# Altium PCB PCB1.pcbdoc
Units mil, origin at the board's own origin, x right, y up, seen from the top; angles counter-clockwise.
Board outline 5280 x 4787.5 mil, 2 copper layers (Top Layer, Bottom Layer); 106 components, 47 nets, 277 pads, 72 vias.
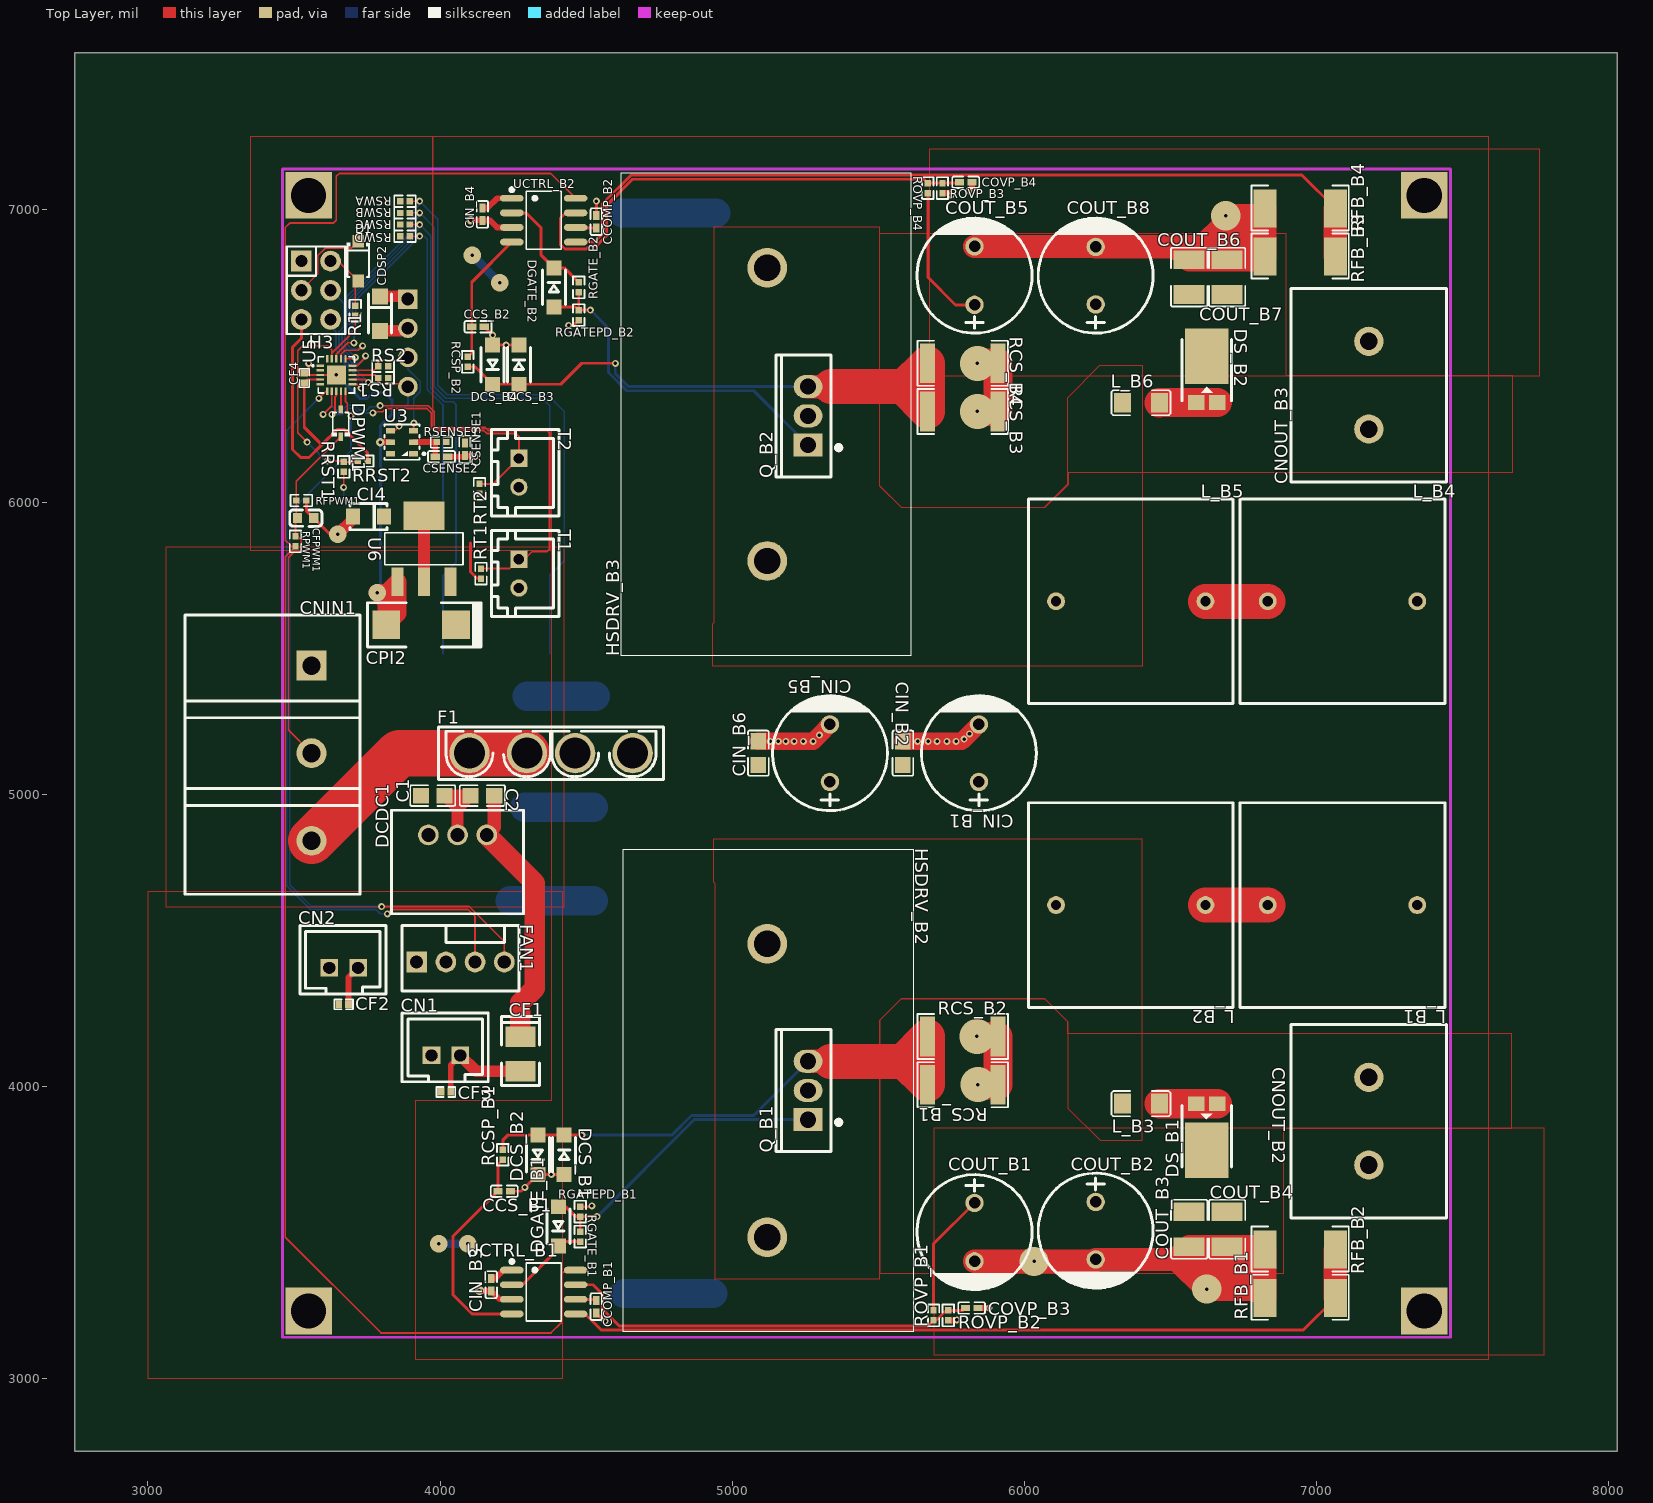
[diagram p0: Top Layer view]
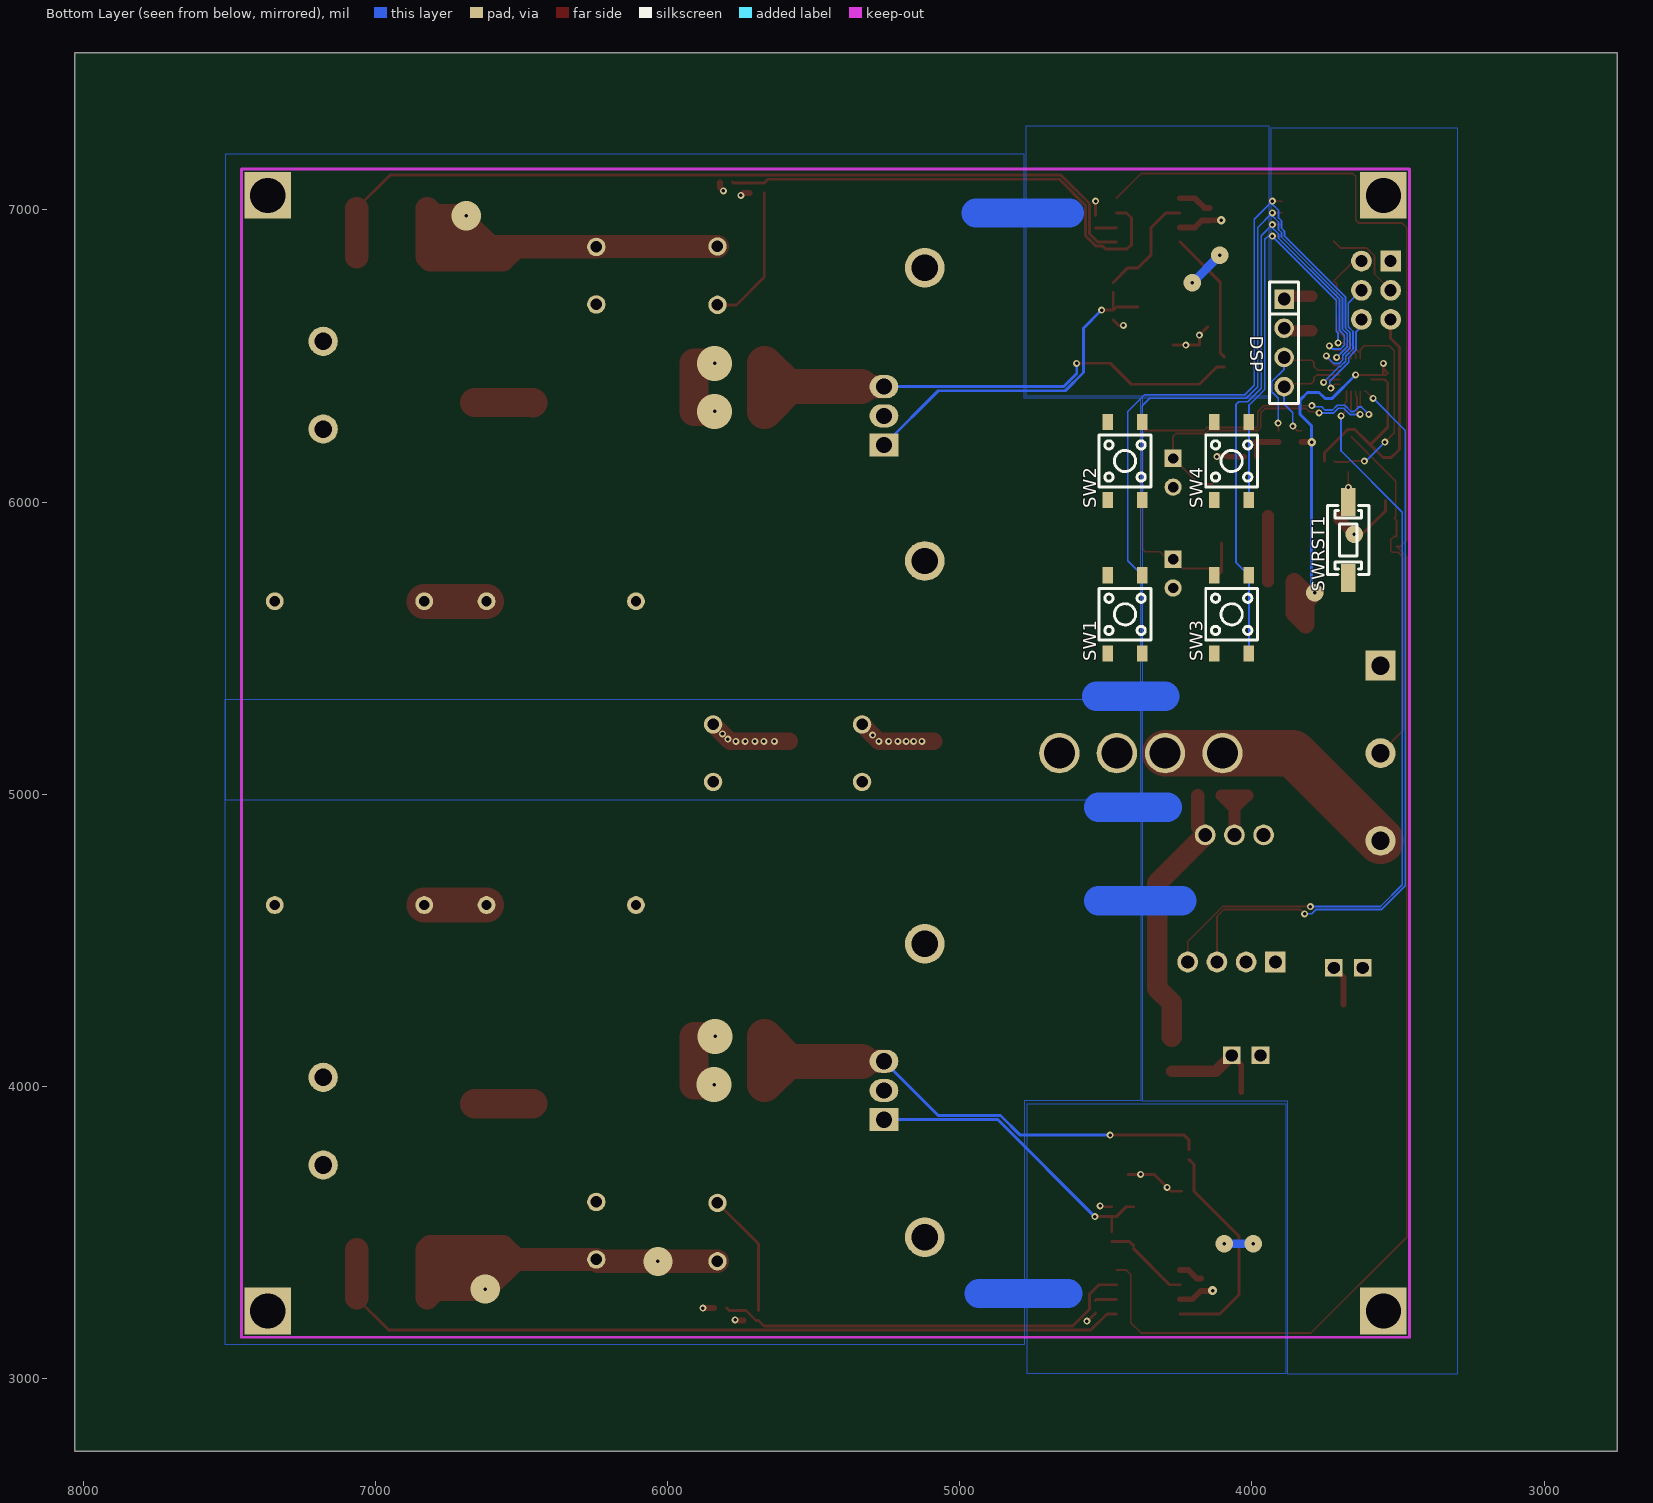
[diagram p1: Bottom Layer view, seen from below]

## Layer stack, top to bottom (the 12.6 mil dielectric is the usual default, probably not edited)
Top Layer: signal copper (thickness not stored)
Dielectric: dielectric 12.6, FR-4, Dk 4.8
Bottom Layer: signal copper (thickness not stored)

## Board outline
8030,2750 2750,2750 2750,7537.5 8030,7537.5

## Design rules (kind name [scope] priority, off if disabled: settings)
Clearance copperThickness1oz [All] p1: gap=7 ignorepadtopadclearanceinfootprint=FALSE except(1: Track-Sheet SMDPad-Sheet THPad-Sheet Via-Sheet Fill-Sheet Region-Sheet Poly-Sheet Text-Sheet Sheet-Hole; 4: Track-Track; 6: Track-SMDPad SMDPad-SMDPad Track-THPad SMDPad-THPad THPad-THPad Track-Via SMDPad-Via THPad-Via Via-Via Track-Fill SMDPad-Fill THPad-Fill Via-Fill Fill-Fill SMDPad-Region THPad-Region Via-Region Fill-Region Region-Region Track-Poly SMDPad-Poly THPad-Poly Via-Poly Fill-Poly Poly-Poly Track-Text SMDPad-Text THPad-Text Via-Text Fill-Text Region-Text Poly-Text Text-Text Track-Hole SMDPad-Hole THPad-Hole Via-Hole Fill-Hole Region-Hole Poly-Hole Text-Hole; 11.8: Track-Region Region-Poly)
Clearance copperThickness2oz [All] p1: gap=7 ignorepadtopadclearanceinfootprint=FALSE except(6: Track-SMDPad SMDPad-SMDPad Track-THPad SMDPad-THPad THPad-THPad Track-Via SMDPad-Via THPad-Via Via-Via Track-Fill SMDPad-Fill THPad-Fill Via-Fill Fill-Fill SMDPad-Region THPad-Region Via-Region Fill-Region Region-Region Track-Poly SMDPad-Poly THPad-Poly Via-Poly Fill-Poly Poly-Poly Track-Text SMDPad-Text THPad-Text Via-Text Fill-Text Region-Text Poly-Text Text-Text Track-Hole SMDPad-Hole THPad-Hole Via-Hole Fill-Hole Region-Hole Poly-Hole Text-Hole; 8: Track-Track; 11.8: Track-Region Region-Poly Track-Sheet SMDPad-Sheet THPad-Sheet Via-Sheet Fill-Sheet Region-Sheet Poly-Sheet Text-Sheet Sheet-Hole)
DiffPairsRouting differentialPair [All] p1: maxuncoupledlength=10 maxlimit=6 mostfreqgap=6 toplayer_minwidth=5 toplayer_prefwidth=10 toplayer_maxwidth=100 bottomlayer_minwidth=5 bottomlayer_prefwidth=10 bottomlayer_maxwidth=100
PasteMaskExpansion pasteMaskExpansion [All] p1:
PlaneConnect innerPlane [All] p1: planeconnectstyle=Relief reliefexpansion=20 reliefentries=4 reliefconductorwidth=10 reliefairgap=10
PolygonConnect copperRegion [All] p1: connectstyle=Relief reliefentries=4 reliefconductorwidth=10 polygonreliefangle="90 Angle" airgapwidth=10
RoutingVias viaSize [All] p1: viastyle="Through Hole" holewidth=12 minholewidth=11.8 maxholewidth=248 width=24 minwidth=19.7 maxwidth=393.7
SolderMaskExpansion solderMaskExpansion [All] p1: useseparateexpansions=TRUE expansion=2 expansionbottom=2
Width copperThickness1oz [All] p1: maxlimit=200 minlimit=5 preferedwidth=10
Width copperThickness2oz [All] p1: maxlimit=100 minlimit=8 preferedwidth=10

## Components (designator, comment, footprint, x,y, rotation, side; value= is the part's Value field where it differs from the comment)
C1 "CGA0805X5R226M350MT" C0805 3975,4995 r0 top
C2 "CL21A226MAYNNNE" C0805 4145,4995 r180 top
CCOMP_B1 "CL05A224KA5NNNC" C0402 4535,3245 r270 top
CCOMP_B2 "CL05A224KA5NNNC" C0402 4535,6960 r90 top
CCS_B1 "TCC0402COG101K500AT" C0402 4220,3640 r0 top
CCS_B2 "TCC0402COG101K500AT" C0402 4130,6600 r0 top
CDSP2 "10uF" CAP-SMD_L3.2-W1.6-R-RD 3795,6645 r90 top
CF1 "10uF" CAP-SMD_L3.5-W2.8 4275,4110 r270 top
CF2 "1uF" 0402 3670,4280 r0 top
CF3 "1uF" 0402 4020,3980 r0 top
CF4 "1uF" 0402 3535,6425 r90 top
CFPWM1 "FN18X102K500PSG" C0603 3540,5945 r180 top
CI4 "10uF" CAP-SMD_L3.2-W1.6 3755,5950 r180 top
CIN_B1 "1010631012R00" CAP-TH_BD10.0-P5.00-D0.6-FD-A 5845,5140 r90 top
CIN_B2 "CL21A106KAYNNNE_C15850" C0805 5585,5140 r90 top
CIN_B3 "CL05A105KA5NQNC" C0402 4175,3320 r90 top
CIN_B4 "CL05A105KA5NQNC" C0402 4145,6985 r90 top
CIN_B5 "1010631012R00" CAP-TH_BD10.0-P5.00-D0.6-FD-A 5335,5140 r90 top
CIN_B6 "CL21A106KAYNNNE_C15850" C0805 5090,5140 r90 top
CN1 "WAFER-XH2.54-2PZZ" CONN-TH_XH2.54-2P 4020,4105 r0 top
CN2 "WAFER-XH2.54-2PZZ" CONN-TH_XH2.54-2P 3670,4405 r0 top
CNIN1 "DBT50G-7.62-3P-BK-P" CONN-TH_3P-P7.62_L15.2-W24.4-EX4.2 3560,5140 r270 top
CNOUT_B2 "WJ25C-B-2P" CONN-TH_2P-P7.62_WJ25C-B-7.62-2P 7180,3880 r270 top
CNOUT_B3 "WJ25C-B-2P" CONN-TH_2P-P7.62_WJ25C-B-7.62-2P 7180,6400 r90 top
COUT_B1 "RG063M331LO10*20TA-1A1E" CAP-TH_BD10.0-P5.00-D1.0-FD 5830,3500 r270 top
COUT_B2 "SPZ1JM221G15O00RAXXX" CAP-TH_BD10.0-P5.00-D0.6-FD-A 6245,3505 r270 top
COUT_B3 "FS32X475K101EGG" C1210 6565,3510 r90 top
COUT_B4 "FS32X475K101EGG" C1210 6695,3510 r90 top
COUT_B5 "RG063M331LO10*20TA-1A1E" CAP-TH_BD10.0-P5.00-D1.0-FD 5830,6775 r90 top
COUT_B6 "FS32X475K101EGG" C1210 6565,6770 r270 top
COUT_B7 "FS32X475K101EGG" C1210 6695,6770 r270 top
COUT_B8 "SPZ1JM221G15O00RAXXX" CAP-TH_BD10.0-P5.00-D0.6-FD-A 6245,6775 r90 top
COVP_B3 "0402B471K500NT" C0402 5820,3240 r180 top
COVP_B4 "0402B471K500NT" C0402 5800,7095 r180 top
CPI2 "TAJC106K035RNJ" CASE-C_6032 3935,5580 r0 top
CSENSE1 "CL05A106MQ5NUNC" C0402 4085,6180 r90 top
CSENSE2 "100nF" C0402 4005,6155 r180 top
D1 "B5819W_C2943878" SOD-123F_L2.7-W1.6-LS3.8-RD-1 3720,6825 r270 top
DCDC1 "K7812-1000_C5199013" PWRM-TH_K78XX-1000 4060,4860 r0 top
DCS_B1 "MMSD4148T3G" SOD-123FL_L2.6-W1.6-LS3.4-RD 4425,3765 r270 top
DCS_B2 "MMSD4148T3G" SOD-123FL_L2.6-W1.6-LS3.4-RD 4335,3765 r90 top
DCS_B3 "MMSD4148T3G" SOD-123FL_L2.6-W1.6-LS3.4-RD 4270,6470 r270 top
DCS_B4 "MMSD4148T3G" SOD-123FL_L2.6-W1.6-LS3.4-RD 4180,6470 r90 top
DGATE_B1 "MMSD4148T3G" SOD-123FL_L2.6-W1.6-LS3.4-RD 4405,3520 r90 top
DGATE_B2 "MMSD4148T3G" SOD-123FL_L2.6-W1.6-LS3.4-RD 4390,6735 r270 top
DPWM1 "CUS08F30,H3F" SOD-323F_L2.0-W1.6-LS2.5-RD 3660,6270 r90 top
DS_B1 "ST2045" TO-277_3P-L5.4-W4.0-LS6.5-BR 6625,3860 r90 top
DS_B2 "ST2045" TO-277_3P-L5.4-W4.0-LS6.5-BR 6625,6420 r270 top
DSP "2.54-1*4P母" HDR-TH_4P-P2.54-V-F 3890,6545 r270 bottom
F1 "XF-507P" CONN-TH_XF-507P 4380,5140 r0 top
FAN1 "HF1004E" CONN-TH_4P-P2.54_HF1004E 4070,4425 r0 top
H3 "Header-Male-2.54_2x3" HDR-TH_6P-P2.54-V-M-R2-C3-S2.54-1 3575,6725 r270 top
HSDRV_B2 "XSD366-094" xsd366094 5120,3985 r270 top
HSDRV_B3 "XSD366-094" xsd366094 5120,6300 r90 top
L_B1 "PDPMAA1712-470MP" IND-TH_L17.8-W17.8-P13.00-D0.6 7090,4620 r180 top
L_B2 "PDPMAA1712-470MP" IND-TH_L17.8-W17.8-P13.00-D0.6 6365,4620 r180 top
L_B3 "HCB3216KF-300T80" L1206 6400,3940 r0 top
L_B4 "PDPMAA1712-470MP" IND-TH_L17.8-W17.8-P13.00-D0.6 7090,5660 r180 top
L_B5 "PDPMAA1712-470MP" IND-TH_L17.8-W17.8-P13.00-D0.6 6365,5660 r180 top
L_B6 "HCB3216KF-300T80" L1206 6400,6340 r0 top
Q_B1 "LPN1510C" TO-220-3_L10.0-W4.5-P2.54-L 5260,3985 r90 top
Q_B2 "LPN1510C" TO-220-3_L10.0-W4.5-P2.54-L 5260,6295 r90 top
R1 "0402WGJ0471TCE" R0402 3710,6655 r270 top
RCS_B1 "MA251230FR060FZ" R2512 5790,4005 r180 top
RCS_B2 "MA251230FR060FZ" R2512 5790,4170 r180 top
RCS_B3 "MA251230FR060FZ" R2512 5790,6310 r180 top
RCS_B4 "MA251230FR060FZ" R2512 5790,6475 r180 top
RCSP_B1 "0402WGJ0101TCE" R0402 4215,3765 r90 top
RCSP_B2 "0402WGJ0101TCE" R0402 4095,6480 r270 top
RFB_B1 "HoLR2512-130mR-1%" RES-SMD_L6.4-W3.2-R2512 6945,3275 r0 top
RFB_B2 "HoLR2512-130mR-1%" RES-SMD_L6.4-W3.2-R2512 6945,3440 r0 top
RFB_B3 "HoLR2512-130mR-1%" RES-SMD_L6.4-W3.2-R2512 6945,6840 r0 top
RFB_B4 "HoLR2512-130mR-1%" RES-SMD_L6.4-W3.2-R2512 6945,7005 r0 top
RFPWM1 "SCR0402J20K" R0402 3525,6005 r180 top
RGATE_B1 "0402WGJ0100TCE" R0402 4480,3485 r270 top
RGATE_B2 "0402WGJ0100TCE" R0402 4475,6735 r90 top
RGATEPD_B1 "RTT021002FTH" R0402 4480,3570 r270 top
RGATEPD_B2 "RTT021002FTH" R0402 4475,6640 r90 top
ROVP_B1 "0402WGF3303TCE" R0402 5690,3215 r90 top
ROVP_B2 "SCR0402J13K" R0402 5740,3215 r90 top
ROVP_B3 "SCR0402J13K" R0402 5720,7075 r90 top
ROVP_B4 "0402WGF3303TCE" R0402 5670,7075 r270 top
RPWM1 "1kΩ" R0402 3505,5865 r90 top
RRST1 "100Ω" R0402 3670,6120 r270 top
RRST2 "RTT021002FTH" R0402 3735,6140 r0 top
RS1 "1kΩ" R0402 3805,6425 r0 top
RS2 "1kΩ" R0402 3805,6465 r0 top
RSENSE1 "0402WGJ0221TCE" R0402 4005,6205 r180 top
RSWA "RTT021002FTH" R0402 3880,7030 r180 top
RSWB "RTT021002FTH" R0402 3880,6990 r180 top
RSWC "RTT021002FTH" R0402 3880,6950 r180 top
RSWD "RTT021002FTH" R0402 3880,6910 r180 top
RT1 "10kΩ" R0402 4140,5755 r90 top
RT2 "10kΩ" R0402 4135,6045 r90 top
SW1 "TS4543TP 250gf 009" SW-SMD_4P-L4.5-W4.5-P3.00-LS6.9 4434.52,5615.48 r90 bottom
SW2 "TS4543TP 250gf 009" SW-SMD_4P-L4.5-W4.5-P3.00-LS6.9 4434.52,6140.48 r90 bottom
SW3 "TS4543TP 250gf 009" SW-SMD_4P-L4.5-W4.5-P3.00-LS6.9 4069.52,5615.48 r90 bottom
SW4 "TS4543TP 250gf 009" SW-SMD_4P-L4.5-W4.5-P3.00-LS6.9 4069.52,6140.48 r90 bottom
SWRST1 "TSB008A2518A" SW-SMD_L6.0-W3.5-LS8.2 3670,5870 r90 bottom
T1 "HC-XH-2A-G" CONN-TH_2P-P2.50_HC-XH-2A-G 4270,5755 r270 top
T2 "HC-XH-2A-G" CONN-TH_2P-P2.50_HC-XH-2A-G 4270,6100 r270 top
U3 "AHT20" SENSOR-SMD_L3.0-W3.0-P1.00-BR 3870,6205 r0 top
U5 "ATTINY1616-MNR" QFN-20_L3.0-W3.0-P0.40-BL-EP1.7 3645,6435 r270 top
U6 "SK1117-5.0" SOT-223_L6.5-W3.5-P2.30-LS7.0-BR 3945,5840 r270 top
UCTRL_B1 "AL3353S-13" SOIC-8_L4.9-W3.9-P1.27-LS6.0-BL 4355,3295 r270 top
UCTRL_B2 "AL3353S-13" SOIC-8_L4.9-W3.9-P1.27-LS6.0-BL 4355,6965 r270 top

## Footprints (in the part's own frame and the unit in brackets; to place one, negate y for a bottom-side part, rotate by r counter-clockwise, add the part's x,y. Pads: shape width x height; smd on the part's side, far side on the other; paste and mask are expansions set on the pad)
0402 [mm]
  rect 0.6x0.65 smd: 1(-0.424,0) 2(0.424,0)
  silkscreen extent -0.82,-0.43 0.81,0.43
C0402 [mm]
  rect 0.79x0.54 smd: 1(-0.545,0) 2(0.545,0)
  silkscreen extent -1.17,-0.5 1.17,0.5
C0603 [mm]
  rect 0.8x0.9 smd: 1(-0.7,0) 2(0.7,0)
  silkscreen extent -1.41,-0.71 1.39,0.72
C0805 [mm]
  rect 1.41x1.35 smd: 1(-1.03,0) 2(1.03,0)
  silkscreen extent -1.96,-0.9 1.96,0.9
C1210 [mm]
  rect 1.635x2.7 smd: 1(-1.517,0) 2(1.517,0)
  silkscreen extent -2.56,-1.58 2.56,1.58
CAP-SMD_L3.2-W1.6 [mm]
  rect 1.2x1.4 smd: 1(-1.35,0) 2(1.35,0)
  silkscreen extent -1.6,-1.14 1.6,1.14
CAP-SMD_L3.2-W1.6-R-RD [mm]
  rect 1.4x1.4 smd: 1(1.5,0) 2(-1.5,0)
  silkscreen extent -1.7,-1 1.7,1
CAP-SMD_L3.5-W2.8 [mm]
  rect 1.8x2.6 smd: 1(-1.501,0) 2(1.501,0)
  silkscreen extent -3.26,-1.65 2.73,1.65
CAP-TH_BD10.0-P5.00-D0.6-FD-A [mm]
  round 1.6 hole 1: 1(-2.5,0) 2(2.5,0)
  silkscreen extent -5,-5 5.08,5
CAP-TH_BD10.0-P5.00-D1.0-FD [mm]
  round 1.6 hole 1: 1(-2.54,0) 2(2.54,0)
  silkscreen extent -5,-5 5.08,5
CASE-C_6032 [mil]
  rect 95.5x98.42 smd: 1(119,0) 2(-119,0)
  silkscreen extent -184,-76 205,75
CONN-TH_2P-P2.50_HC-XH-2A-G [mm]
  rect 1.524x1.5 hole 0.9: 1(-1.25,0)
  round 1.5 hole 0.9: 2(1.25,0)
  silkscreen extent -3.75,-2.4 3.75,3.5
CONN-TH_2P-P7.62_WJ25C-B-7.62-2P [mil]
  round 100 hole 60: 1(-150.1,0) 2(150.1,0)
  silkscreen extent -331,-266 331,266
CONN-TH_3P-P7.62_L15.2-W24.4-EX4.2 [mm]
  rect 2.6x2.6 hole 1.6: 1(-7.62,0)
  round 2.6 hole 1.6: 2(0,0) 3(7.62,0)
  silkscreen extent -12.03,-11 12.27,4.2
CONN-TH_4P-P2.54_HF1004E [mm]
  rect 1.8x1.8 hole 1.14: 1(-3.81,0)
  round 1.8 hole 1.14: 2(-1.27,0) 3(1.27,0) 4(3.81,0)
  silkscreen extent -5.08,-2.54 5.08,3.18
CONN-TH_XF-507P [mm]
  round 3.5 hole 2.7: 1(-7.1,0) 2(-2.1,0) 3(2.1,0) 4(7.1,0)
  silkscreen extent -9.78,-2.29 9.78,2.29
CONN-TH_XH2.54-2P [mil]
  rect 60x60 hole 39.37 slot 41.34 at 0 deg: 1(-49.22,0) 2(49.22,0)
  silkscreen extent -150,-90 145,145
HDR-TH_4P-P2.54-V-F [mm]
  rect 1.7x1.7 hole 1.1: 1(-3.81,0)
  round 1.7 hole 1.1: 2(-1.27,0) 3(1.27,0) 4(3.81,0)
  silkscreen extent -5.29,-1.27 5.29,1.27
HDR-TH_6P-P2.54-V-M-R2-C3-S2.54-1 [mm]
  rect 1.8x1.8 hole 1.05: 1(-2.54,-1.27)
  round 1.8 hole 1.05: 2(-2.54,1.27) 3(0,-1.27) 4(0,1.27) 5(2.54,-1.27) 6(2.54,1.27)
  silkscreen extent -3.81,-2.54 3.81,2.54
IND-TH_L17.8-W17.8-P13.00-D0.6 [mm]
  round 1.55 hole 0.9: 1(-6.5,0) 2(6.5,0)
  silkscreen extent -8.9,-8.9 8.9,8.9
L1206 [mm]
  rect 1.485x1.728 smd: 1(-1.593,0) 2(1.593,0)
  silkscreen extent -2.56,-1.09 2.56,1.09
PWRM-TH_K78XX-1000 [mm]
  round 1.8 hole 1.2: 1(-2.54,0) 2(0,0) 3(2.54,0)
  silkscreen extent -5.75,-6.85 5.75,2.15
QFN-20_L3.0-W3.0-P0.40-BL-EP1.7 [mm]
  rect 0.2x0.665 smd: 1(-0.8,-1.407) 2(-0.4,-1.407) 3(0,-1.407) 4(0.4,-1.407) 5(0.8,-1.407) 11(0.8,1.407) 12(0.4,1.407) 13(0,1.407) 14(-0.4,1.407) 15(-0.8,1.407)
  rect 0.665x0.2 smd: 6(1.407,-0.8) 7(1.407,-0.4) 8(1.407,0) 9(1.407,0.4) 10(1.407,0.8) 16(-1.407,0.8) 17(-1.407,0.4) 18(-1.407,0) 19(-1.407,-0.4) 20(-1.407,-0.8)
  rect 1.65x1.65 smd: 21(0,0)
  silkscreen extent -1.58,-2.11 1.58,1.58
R0402 [mm]
  rect 0.566x0.54 smd: 1(-0.433,0) 2(0.433,0)
  silkscreen extent -0.94,-0.5 0.94,0.5
R2512 [mil]
  rect 50.49x136.06 smd: 1(-120.72,0) 2(120.72,0)
  silkscreen extent -155,-77 155,77
RES-SMD_L6.4-W3.2-R2512 [mm]
  rect 2x3.3 smd: 1(-3.066,0) 2(3.066,0)
  silkscreen extent -4.23,-1.91 4.23,2.01
SENSOR-SMD_L3.0-W3.0-P1.00-BR [mm]
  rect 0.8x0.5 smd: 1(1,-1) 2(1,0) 3(1,1) 4(-1,1) 5(-1,0) 6(-1,-1)
  silkscreen extent -1.52,-1.52 2,1.52
SOD-123F_L2.7-W1.6-LS3.8-RD-1 [mm]
  rect 1.1x1 smd: 1(-1.735,0) 2(1.735,0)
  silkscreen extent -1.6,-1 1.38,1
SOD-123FL_L2.6-W1.6-LS3.4-RD [mm]
  rect 1.3x1.3 smd: 1(-1.7,0) 2(1.7,0)
  silkscreen extent -1.5,-1 1.5,1
SOD-323F_L2.0-W1.6-LS2.5-RD [mm]
  rect 0.73x0.385 smd: 1(-1.185,0) 2(1.185,0)
  silkscreen extent -1.15,-0.78 0.93,0.78
SOIC-8_L4.9-W3.9-P1.27-LS6.0-BL [mm]
  oval 0.588x2.045 smd: 1(-1.905,-2.772) 2(-0.635,-2.772) 3(0.635,-2.772) 4(1.905,-2.772) 5(1.905,2.772) 6(0.635,2.772) 7(-0.635,2.772) 8(-1.905,2.772)
  silkscreen extent -2.8,-2.92 2.53,1.52
SOT-223_L6.5-W3.5-P2.30-LS7.0-BR [mm]
  rect 2.465x1.05 smd: 1(2.858,-2.3) 2(2.857,0) 3(2.857,2.3)
  rect 2.465x3.54 smd: 4(-2.857,0)
  silkscreen extent -1.4,-3.4 1.4,3.4
SW-SMD_4P-L4.5-W4.5-P3.00-LS6.9 [mm]
  rect 1.4x0.9 smd: 1(-3.4,1.5) 2(3.4,1.5) 3(-3.4,-1.5) 4(3.4,-1.5)
  silkscreen extent -2.25,-2.25 2.25,2.25
SW-SMD_L6.0-W3.5-LS8.2 [mm]
  rect 2.42x1.28 smd: 1(-3.296,0) 2(3.296,0)
  silkscreen extent -2.99,-1.8 3.01,1.8
TO-220-3_L10.0-W4.5-P2.54-L [mm]
  rect 2x2.5 hole 1.4: 1(-2.54,0)
  oval 2x2.5 hole 1.4: 2(0,0) 3(2.54,0)
  silkscreen extent -5.3,-2.86 5.3,2.8
TO-277_3P-L5.4-W4.0-LS6.5-BR [mil]
  rect 50.8x56 smd: 1(79.39,-36.22) 3(79.39,36.22)
  rect 188.98x149.61 smd: 2(-79.39,0)
  silkscreen extent -137,-85 73,85
xsd366094 [mm]
  round 3.45 hole 2.3: 1(-12.75,0) 2(12.75,0)
  silkscreen extent -21,-12.5 21,12.7

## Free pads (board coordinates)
  rect 160x160 hole 120: 33(3550,3230) 33(3550,7050) 33(7370,3230) 33(7370,7050)

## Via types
v1: diameter 24, hole 12, Top Layer to Bottom Layer, 55 vias
v2: diameter 60, hole 12.01, Top Layer to Bottom Layer, 4 vias
v3: diameter 120, hole 12, Top Layer to Bottom Layer, 4 vias
v4: diameter 100, hole 11.81, Top Layer to Bottom Layer, 2 vias
v5: diameter 30, hole 12, Top Layer to Bottom Layer, 2 vias
v6: diameter 60, hole 12, Top Layer to Bottom Layer, 2 vias
v7: diameter 30, hole 11.81, Top Layer to Bottom Layer, 1 vias
v8: diameter 24, hole 11.81, Top Layer to Bottom Layer, 1 vias
v9: diameter 100, hole 12, Top Layer to Bottom Layer, 1 vias

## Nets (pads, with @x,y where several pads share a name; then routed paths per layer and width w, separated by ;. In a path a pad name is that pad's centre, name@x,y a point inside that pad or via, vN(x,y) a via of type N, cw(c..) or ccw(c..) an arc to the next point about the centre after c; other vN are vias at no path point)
$1N8682: DS_B1.1 DS_B1.3 L_B3.2 | length 198.8
  Top Layer w100: L_B3.2 6463.31,3939.39 DS_B1.3 DS_B1.1
$1N8688: L_B1.2 L_B2.1 | length 213.2
  Top Layer w120: L_B2.1 L_B1.2
$1N8707: CCOMP_B1.1 UCTRL_B1.6 | length 72.3
  Top Layer w10: UCTRL_B1.6 4531.46,3270 CCOMP_B1.1
$1N8712: DGATE_B1.1 RGATE_B1.2 UCTRL_B1.2 | length 291.3
  Top Layer w10: UCTRL_B1.2 4281.93,3320 DGATE_B1.1@4405,3443.07 ; DGATE_B1.1 4419.89,3467.96 RGATE_B1.2
$1N8739: DCS_B1.1 DCS_B2.2 Q_B1.3 RCS_B1.2 RCS_B2.2 RCSP_B1.2 | length 1917.4
  Top Layer w10: RCSP_B1.2 4215,3815 4231.93,3831.93 DCS_B2.2 DCS_B1.1 v1(4485.33,3831.93)
  Top Layer w80: Q_B1.3 5337.27,4085
  Top Layer w120: 5337.27,4085 5584.28,4085 ; 5584.28,4085 RCS_B2.2 RCS_B1.2 5589.28,4085 5584.28,4085
  Bottom Layer w10: v1(4485.33,3831.93) 4793.48,3831.93 4860.57,3899.02 5074.02,3899.02 Q_B1.3
$1N8772: DGATE_B1.2 Q_B1.1 RGATE_B1.1 RGATEPD_B1.2 | length 1057.5
  Top Layer w10: DGATE_B1.2 4430.4,3586.93 4464.37,3552.96 RGATEPD_B1.2 ; RGATE_B1.1 RGATEPD_B1.2 ; v1(4537.96,3552.96) RGATEPD_B1.2
  Bottom Layer w10: v1(4537.96,3552.96) 4870,3885 Q_B1.1
$1N8790: CCS_B1.1 RCSP_B1.1 UCTRL_B1.4 | length 761.2
  Top Layer w10: RCSP_B1.1 4198.54,3731.5 CCS_B1.1 4045,3486.46 4045,3285 4110,3220 UCTRL_B1.4
$1N8797: COVP_B3.2 ROVP_B1.1 ROVP_B2.2 UCTRL_B1.7 | length 1448.2
  Top Layer w10: UCTRL_B1.7 4523.96,3320 4556.63,3287.33 4556.63,3235.9 4613.51,3179.02 5671.06,3179.02 ROVP_B1.1 5697.96,3197.96 5732.04,3232.04 ROVP_B2.2 5790.58,3232.04 COVP_B3.2
$1N25369: D1.1 H3.3 | length 301.5
  Top Layer w6: H3.3 3580.57,6780.57 3580.57,6843.4 3606.6,6869.43 3696.13,6869.43 D1.1
$1N25378: D1.2 H3.2 R1.1 | length 212.1
  Top Layer w6: H3.2 3651.7,6825 D1.2 3710,6746.69 R1.1
$1N26156: RRST1.2 SWRST1.2 | length 103.2
  Top Layer w6: v1(3670,6050) RRST1.2
  Bottom Layer w6: SWRST1.2 v1(3670,6050)
$1N34640: DS_B2.1 DS_B2.3 L_B6.2 | length 198.8
  Top Layer w100: L_B6.2 6463.31,6340.61 DS_B2.1 DS_B2.3
$1N34641: L_B4.2 L_B5.1 | length 213.2
  Top Layer w120: L_B5.1 L_B4.2
$1N34643: CCOMP_B2.1 UCTRL_B2.6 | length 71.5
  Top Layer w10: UCTRL_B2.6 4465.61,6938.54 CCOMP_B2.1
$1N34645: DGATE_B2.1 RGATE_B2.2 UCTRL_B2.2 | length 382.2
  Top Layer w10: UCTRL_B2.2 4295,6990 4345,6940 4345,6846.93 DGATE_B2.1 4425.11,6801.93 RGATE_B2.2
$1N34649: DGATE_B2.2 Q_B2.1 RGATE_B2.1 RGATEPD_B2.2 | length 1215.9
  Top Layer w10: DGATE_B2.2 4463.97,6668.07 RGATEPD_B2.2 ; RGATE_B2.1 RGATEPD_B2.2 ; v1(4515,6657.04) RGATEPD_B2.2
  Bottom Layer w10: v1(4515,6657.04) 4577,6595.04 4577,6443 4639,6381 5074,6381 Q_B2.1
$1N34651: CCS_B2.1 RCSP_B2.1 UCTRL_B2.4 | length 455.4
  Top Layer w10: RCSP_B2.1 4108.54,6510.58 CCS_B2.1 4108.54,6752.69 UCTRL_B2.4
$1N34652: COVP_B4.2 ROVP_B3.2 ROVP_B4.1 UCTRL_B2.7 | length 1688.7
  Top Layer w10: UCTRL_B2.7 4430,6990 4412.89,6972.89 4412.89,6880.65 4427.54,6866 4500.76,6866 4510.76,6876 4534,6876 4570.63,6912.63 4570.63,7016.38 4659.25,7105 5657.04,7105 ROVP_B4.1 ROVP_B3.2 5775.58,7092.04 COVP_B4.2
$1N34653: DCS_B3.2 DCS_B4.1 Q_B2.3 RCS_B3.2 RCS_B4.2 RCSP_B2.2 | length 2001
  Top Layer w10: RCSP_B2.2 4120.11,6462.96 DCS_B4.1 DCS_B3.2 4413.07,6403.07 4485,6475 v1(4600,6475)
  Top Layer w80: Q_B2.3 5339,6395
  Top Layer w120: 5339,6395 5584.28,6395 ; 5584.28,6395 5589.28,6395 RCS_B4.2 RCS_B3.2 5584.28,6395
  Bottom Layer w10: v1(4600,6475) 4600,6439.8 4644.8,6395 Q_B2.3
+5V: CDSP2.1 CF4.1 CI4.1 CSENSE1.2 DSP.1 H3.5 RRST2.2 RS1.2 RS2.2 RSENSE1.1 RSWA.2 RSWB.2 RSWC.2 RSWD.2 RT1.1 RT2.1 U5.4 U6.2 U6.4 | length 1592.4
  Top Layer w8: CF4.1 3545.95,6419.25 U5.4
  Top Layer w10: H3.5 3525,6560 3495,6530 3495,6180 3522.93,6152.07 3551.22,6152.07 3594.88,6195.74 ; CF4.1 3535,6255.62 3594.88,6195.74 ; RRST2.2 3752.04,6168.81 3672.13,6248.72 3647.87,6248.72 3594.88,6195.74 ; 4105,5860 4105,5760 4127.04,5737.96 RT1.1
  Top Layer w40: CDSP2.1 3880.95,6704.05 DSP.1 ; U6.2 U6.4
+12V: C2.1 CF1.1 CF2.1 CF3.1 CN1.1 CN2.1 DCDC1.3 FAN1.1 | length 925.5
  Top Layer w45: DCDC1.3 4185.55,4885.55 C2.1
  Top Layer w70: DCDC1.3 4325,4695 4325,4335 4275,4285 CF1.1
AGND: C1.2 C2.2 CCOMP_B1.2 CCOMP_B2.2 CCS_B1.2 CCS_B2.2 CDSP2.2 CF1.2 CF2.2 CF3.2 CF4.2 CFPWM1.1 CI4.2 CIN_B1.2 CIN_B2.2 CIN_B3.1 CIN_B4.1 CIN_B5.2 CIN_B6.2 CN1.2 CN2.2 CNIN1.1 COUT_B1.2 COUT_B2.2 COUT_B3.1 COUT_B4.1 COUT_B5.2 COUT_B6.1 COUT_B7.1 COUT_B8.2 COVP_B3.1 COVP_B4.1 CPI2.2 CSENSE1.1 CSENSE2.1 DCDC1.2 DCS_B1.2 DCS_B2.1 DCS_B3.1 DCS_B4.2 DSP.2 FAN1.2 H3.1 pad.33 RCS_B1.1 RCS_B2.1 RCS_B3.1 RCS_B4.1 RFB_B1.1 RFB_B2.1 RFB_B3.1 RFB_B4.1 RFPWM1.1 RGATEPD_B1.1 RGATEPD_B2.1 ROVP_B2.1 ROVP_B3.1 SW1.1 SW1.2 SW2.1 SW2.2 SW3.1 SW3.2 SW4.1 SW4.2 SWRST1.1 T1.2 T2.2 U3.5 U5.3 U5.21 U6.1 UCTRL_B1.3 UCTRL_B2.3 | length 10891.5
  Top Layer w8: v1(3550,6475) 3550,6456.7 ; v1(3645,6435) U5.3 3550.97,6435 ; 3550,6456.7 CF4.2 3541.7,6435 3550.97,6435 ; 3550,6456.7 3550,6435.97 3550.97,6435
  Top Layer w10: RFPWM1.1 3542.04,5970 3567.04,5945 CFPWM1.1 3622.56,5890 v6(3650,5890) ; CCS_B2.2 v1(4180,6571.46) DCS_B4.2 v1(4225.94,6536.93) DCS_B3.1 ; CCS_B1.2 4276.93,3640 v1(4290.19,3653.26) DCS_B2.1 v1(4380.85,3698.07) DCS_B1.2 ; v1(4440,6605) 4457.04,6605 RGATEPD_B2.1 ; RGATEPD_B1.1 4517.04,3587.04 v1(4520,3590) ; CCOMP_B1.2 4563.54,3195 v8(4565,3195) ; CCOMP_B2.2 v1(4535,7030)
  Top Layer w20: CF2.2 3686.7,4372.48 CN2.2 ; v5(3795.56,6205.01) U3.5 ; CSENSE2.1 4081.46,6155 CSENSE1.1 4116.46,6158.54 v1(4120,6155) ; CF3.2 4036.7,4072.49 CN1.2 ; v5(4105,6965) 4143.54,6965 CIN_B4.1 4172.05,6963.54 4195.59,6940 UCTRL_B2.3 ; v7(4135,3300) 4136.46,3298.54 CIN_B3.1 4203.54,3270 UCTRL_B1.3 ; ROVP_B3.1 5742.04,7057.96 v1(5750,7050) ; ROVP_B2.1 5767.96,3197.96 v1(5770,3200) ; v1(5810,7065) 5821.46,7076.46 COVP_B4.1 ; COVP_B3.1 v1(5880,3240)
  Top Layer w40: v6(3650,5890) 3701.85,5941.85 CI4.2 ; CDSP2.2 3880.94,6585.94 DSP.2 ; DCDC1.2 4060,4950.55 ; CN1.2 4123.31,4050.9 CF1.2 ; 4060,4950.55 C2.2 C1.2 4060,4950.55
  Top Layer w60: CIN_B6.2 v1(5130.55,5180.55) v1(5158.34,5180.55) v1(5184.48,5180.55) v1(5212.32,5180.55) v1(5244.38,5180.55) v1(5277.12,5180.55) v1(5298.62,5202.05) CIN_B5.2 ; CIN_B2.2 v1(5634.92,5180.55) v1(5670.89,5180.55) v1(5702.29,5180.55) v1(5735.65,5180.55) v1(5767.05,5180.55) 5787.12,5180.55 v1(5812.86,5206.29) CIN_B1.2 ; v6(3785,5690) 3816,5659 CPI2.2 3854.45,5618.45 U6.1 3816.95,5690 v6(3785,5690)
  Top Layer w80: COUT_B1.2 v4(6034.1,3400) 6238.43,3400 COUT_B2.2 6521.31,3406.57 ; COUT_B5.2 6243.43,6875 COUT_B8.2 6521.31,6873.43 ; 6521.31,3406.57 COUT_B3.1 ; 6521.31,3406.57 6523.43,3406.57 v4(6625,3305) ; 6521.31,6873.43 COUT_B6.1 ; 6521.31,6873.43 6608.69,6873.43 ; COUT_B3.1 COUT_B4.1 ; COUT_B3.1 6625,3390.26 v4(6625,3305) ; COUT_B6.1 COUT_B7.1@6649.02,6829.74 ; COUT_B6.1 6608.69,6873.43 ; 6608.69,6873.43 6690,6954.74 v9(6690,6980) RFB_B4.1@6799.28,6980 ; 6608.69,6873.43 6692.7,6873.43 ; v4(6625,3305) 6695,3375 COUT_B4.1 ; v4(6625,3305) 6689.28,3305 ; COUT_B7.1@6649.02,6829.74 COUT_B7.1 ; COUT_B7.1@6649.02,6829.74 6692.7,6873.43 ; 6689.28,3305 6794.28,3305 RFB_B1.1 RFB_B1.1@6824.28,3320.98 ; 6689.28,3305 6764.77,3380.49 ; 6692.7,6873.43 6738.69,6873.43 ; 6692.7,6873.43 RFB_B4.1@6799.28,6980 ; COUT_B4.1 6814.02,3450.26 RFB_B2.1 ; COUT_B4.1 6764.77,3380.49 ; COUT_B7.1 COUT_B7.1@6705.26,6840 ; COUT_B7.1 6814.02,6829.74 RFB_B3.1 ; COUT_B7.1@6705.26,6840 RFB_B3.1 ; COUT_B7.1@6705.26,6840 6738.69,6873.43 ; 6738.69,6873.43 RFB_B4.1@6824.28,6959.02 ; 6738.69,6873.43 6790.85,6873.43 RFB_B3.1 ; 6764.77,3380.49 RFB_B1.1@6824.28,3320.98 ; 6764.77,3380.49 RFB_B2.1 ; RFB_B4.1@6799.28,6980 RFB_B4.1 RFB_B4.1@6824.28,6959.02 ; RFB_B1.1@6824.28,3320.98 RFB_B2.1 ; RFB_B3.1 RFB_B4.1@6824.28,6959.02
  Top Layer w100: v3(5837.79,4170) RCS_B2.1 RCS_B1.1 v3(5841.25,4005) ; v3(5840,6310) RCS_B3.1 RCS_B4.1 v3(5840,6475)
  Bottom Layer w10: v1(3645,6435) 3725,6355 3750,6355 3770,6375 3810,6375 3835,6350 3835,6300 3795.56,6260.56 v5(3795.56,6205.01) 3795.56,5700.56 v6(3785,5690)
  Bottom Layer w100: 4240,4635 4525,4635 ; 4290,4955 4525,4955 ; 4297.5,5335 4532.5,5335 ; 4625,6990 4945,6990 ; 4630,3290 4935,3290
  other v1: 5794.55,5187.97
MC_PWM_LED: DPWM1.2 U5.9 | length 63.3
  Top Layer w6: DPWM1.2 3660.75,6317.4 U5.9
NTC1: RT1.2 T1.1 U5.7 | length 1631.6
  Top Layer w6: v1(3600,6300) 3629.25,6329.25 U5.7 ; v1(3795,6330) 3959.14,6330 3980,6309.14 3980,6259.14 3984.14,6255 4154.14,6255 4164.14,6245 4365,6245 4375,6235 4375,5840 4365,5830 4315,5830 4289.22,5804.22 T1.1 4237.82,5772.04 RT1.2
  Bottom Layer w6: v1(3600,6300) 3625,6325 3635,6325 3650,6310 3660.86,6310 3681.86,6331 3708.14,6331 3724.14,6315 3750.3,6315 3761.3,6326 3791,6326 v1(3795,6330)
NTC2: RT2.2 T2.1 U5.8 | length 1062.9
  Top Layer w6: v1(3630,6300) 3640,6310 3640,6358.5 3645,6363.5 U5.8 ; v1(3770,6305) 3774,6309 3803.7,6309 3814.7,6320 3955,6320 3970,6305 3970,6255 3980,6245 4150,6245 4160,6235 4260,6235 4270,6225 T2.1 4182.82,6062.04 RT2.2
  Bottom Layer w6: v1(3630,6300) 3665,6300 3686,6321 3704,6321 3720,6305 v1(3770,6305)
PWM_FAN: FAN1.4 U5.10 | length 2670
  Top Layer w6: U5.10 3676.5,6343.5 3682.5,6337.5 3682.5,6307.5 v1(3695,6295) ; v1(3800,4615) 4100,4615 4220,4495 FAN1.4
  Bottom Layer w6: v1(3695,6295) 3695,6175 3485,5965 3485,4690 3560,4615 v1(3800,4615)
PWM_LED: CFPWM1.2 CNIN1.2 DPWM1.1 RFPWM1.2 RPWM1.2 | length 1227.9
  Top Layer w6: CNIN1.2 3480,5220 3480,5808.82 3499.01,5827.82 3519.36,5827.82 3524.63,5833.1 3524.63,5870.9 3513.49,5882.04 RPWM1.2 3505,5937.56 CFPWM1.2 3507.96,5949.48 RFPWM1.2 3507.96,6071.31 DPWM1.1
PWM_LED_O: RPWM1.1 UCTRL_B1.8 UCTRL_B2.8 | length 6003.7
  Top Layer w6: UCTRL_B1.8 4430,3370 4414.89,3354.89 4414.89,3189.89 4380,3155 3797.73,3155 3470,3482.73 3470,5812.96 RPWM1.1 3491.37,5847.96 3470,5869.33 3470,6940 3485,6955 3635,6955 3645,6965 3645,7115 3655,7125 4379.15,7125 UCTRL_B2.8
RPM_FAN: FAN1.3 U5.6 | length 2610.2
  Top Layer w6: v1(3585,6355) 3609.59,6379.59 U5.6 ; v1(3820,4590) 3835,4605 4095.86,4605 4120,4580.86 FAN1.3
  Bottom Layer w6: v1(3585,6355) 3475,6245 3475,4685.86 3555.86,4605 3780,4605 3795,4590 v1(3820,4590)
RX: H3.6 U5.11 | length 317
  Top Layer w6: U5.11 3716.5,6403.5 v1(3730,6390)
  Bottom Layer w6: H3.6 3625,6600 3644,6581 3644,6519.73 3669,6494.73 3669,6478.02 3734,6413.02 3734,6394 v1(3730,6390)
SCL: DSP.3 RS2.1 U3.3 U5.14 | length 493.4
  Top Layer w6: U5.14 3773.71,6450.75 RS2.1 3787.96,6478.12 3794.84,6485 3880,6485 DSP.3 ; U3.3 3909.37,6269.37 v1(3910,6270)
  Bottom Layer w6: DSP.3 3890,6455.05 3932.46,6412.59 3932.46,6377.41 3910,6354.95 v1(3910,6270)
SDA: DSP.4 RS1.1 U3.4 U5.13 | length 395.9
  Top Layer w6: U5.13 3777.96,6435 RS1.1 3787.96,6414 3796.96,6405 3880,6405 DSP.4 ; U3.4 3844.37,6244.37 v1(3860,6260)
  Bottom Layer w6: v1(3860,6260) 3860,6305 3890,6335 DSP.4
SWA: RSWA.1 SW1.3 SW1.4 U5.15 | length 2805.3
  Top Layer w6: U5.15 3716.5,6466.5 3745,6495 v1(3745,6500) ; RSWA.1 v1(3930,7030)
  Bottom Layer w6: v1(3745,6500) 3719,6474 3701.3,6474 3689,6486.3 3689,6503.02 3664,6528.02 3664,6579.86 3680,6595.86 3680,6702.43 3889,6911.43 3889,6926.98 3899,6936.98 3899,6962.84 3909,6972.84 3909,6998.7 3930,7019.7 v1(3930,7030) 3992.02,6967.98 3992.02,6399.98 4024.98,6367.02 4367.98,6367.02 4425,6310 4425,5798.86 SW1.4 SW1.3
SWB: RSWB.1 SW2.3 SW2.4 U5.16 | length 2045.5
  Top Layer w6: U5.16 3705.41,6490.41 v1(3710,6495) ; RSWB.1 v1(3930,6990)
  Bottom Layer w6: v1(3710,6495) 3710,6496.16 3674,6532.16 3674,6575.72 3690,6591.72 3690,6698.28 3899,6907.28 3899,6922.84 3909,6932.84 3909,6958.7 3930,6979.7 v1(3930,6990) 3980,6940 3980,6395 4020,6355 4350,6355 4375.47,6329.53 SW2.4 SW2.3
SWC: RSWC.1 SW3.3 SW3.4 U5.17 | length 2267.1
  Top Layer w6: U5.17 3660.75,6505.75 3675,6520 3720,6520 v1(3735,6535) ; RSWC.1 v1(3930,6950)
  Bottom Layer w6: v1(3735,6535) 3724,6524 3696.3,6524 3684,6536.3 3684,6571.57 3700,6587.57 3700,6694.14 3909,6903.14 3909,6918.7 3930,6939.7 v1(3930,6950) 3967.98,6912.02 3967.98,6390.02 4015.02,6342.98 4045,6342.98 4055,6332.98 4055,5793.86 SW3.4 SW3.3
SWD: RSWD.1 SW4.3 SW4.4 U5.18 | length 1530.4
  Top Layer w6: U5.18 3645,6506.5 3683.5,6545 v1(3705,6545) ; RSWD.1 v1(3930,6910)
  Bottom Layer w6: v1(3705,6545) 3705,6578.43 3711,6584.43 3711,6691 v1(3930,6910) 3945,6910 3955.97,6899.03 3955.97,6385.05 4010.05,6330.97 4010.47,6331.86 SW4.4 SW4.3
TX: H3.4 U5.12 | length 442.8
  Top Layer w6: U5.12 3745.75,6419.25 v1(3755,6410)
  Bottom Layer w6: H3.4 3670,6680 3670,6600 3654,6584 3654,6523.88 3679,6498.88 3679,6482.16 3697.15,6464 3701,6464 v1(3755,6410)
UDPI: R1.2 RRST1.1 RRST2.1 U5.19 | length 850.1
  Top Layer w6: v1(3545,6205) 3513.2,6236.8 3513.2,6518.2 3530,6535 3615,6535 3629.25,6520.75 3629.25,6509.25 ; v1(3615,6140) 3667.04,6140 RRST1.1 3715,6137.04 RRST2.1 ; U5.19 3629.25,6509.25 ; R1.2 3710,6590 3629.25,6509.25
  Bottom Layer w6: v1(3545,6205) 3610,6140 v1(3615,6140)
V+LED_B_1: CNOUT_B2.1 COUT_B1.1 COUT_B2.1 COUT_B3.2 COUT_B4.2 DS_B1.2 ROVP_B1.2 | length 425.9
  Top Layer w10: ROVP_B1.2 5690,3460 COUT_B1.1
V+LED_B_2: CNOUT_B3.1 COUT_B5.1 COUT_B6.2 COUT_B7.2 COUT_B8.1 DS_B2.2 ROVP_B4.2 | length 487.3
  Top Layer w10: ROVP_B4.2 5670,6770 5765,6675 COUT_B5.1
V-LED_B_1: CNOUT_B2.2 RFB_B1.2 RFB_B2.2 UCTRL_B1.5 | length 2834.9
  Top Layer w10: UCTRL_B1.5 4496.8,3220 4551.8,3165 6955.72,3165 RFB_B1.2
  Top Layer w80: RFB_B1.2 RFB_B2.2
V-LED_B_2: CNOUT_B3.2 RFB_B3.2 RFB_B4.2 UCTRL_B2.5 | length 2970.2
  Top Layer w10: UCTRL_B2.5 4528.2,6890 4556.63,6918.43 4556.63,7022.18 4654.45,7120 6950.72,7120 RFB_B4.2
  Top Layer w80: RFB_B3.2 RFB_B4.2
VCC: C1.1 CNIN1.3 CPI2.1 DCDC1.1 F1.1 F1.2 U6.3 | length 861.6
  Top Layer w160: CNIN1.3 3860,5140 F1.1 F1.2
VCCF: 
VDD: CSENSE2.2 RSENSE1.2 U3.2 | length 130.4
  Top Layer w20: U3.2 RSENSE1.2 3983.54,6200.58 CSENSE2.2
VL_B_1: HSDRV_B2.1 HSDRV_B2.2 L_B2.2 L_B3.1 Q_B1.2
VL_B_2: HSDRV_B3.1 HSDRV_B3.2 L_B5.2 L_B6.1 Q_B2.2
pads on no net: CIN_B1.1 CIN_B2.1 CIN_B3.2 CIN_B4.2 CIN_B5.1 CIN_B6.1 F1.3 F1.4 L_B1.1 L_B4.1 U3.1 U3.6 U5.1 U5.2 U5.5 U5.20 UCTRL_B1.1 UCTRL_B2.1
copper on no net: | length 430.8
  Top Layer w20: 4145,7006.46 4162.05,7006.46 4195.59,7040 4245.85,7040 ; 4175,3341.46 4188.63,3341.46 4217.17,3370 4245.85,3370
  Bottom Layer w30: v2(3995.95,3460) v2(4095,3460) ; v2(4110,6845) v2(4205,6750)

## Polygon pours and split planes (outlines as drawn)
AGND on Bottom Layer (solid, remove dead copper, pour order 20): 3885,3015 4770,3015 4770,3940 3885,3940
V-LED_B_1 on Top Layer (solid, remove dead copper, pour order 8): 5690,3080 7780,3080 7780,3855 5690,3855
V-LED_B_2 on Top Layer (solid, remove dead copper, pour order 14): 5675,6432.5 7765,6432.5 7765,7207.5 5675,7207.5
+12V on Top Layer (solid, remove dead copper, pour order 20): 3000,3000 4420,3000 4420,4665 3000,4665
AGND on Bottom Layer (solid, remove dead copper, pour order 44): 3942.5,6362.5 4772.5,6362.5 4772.5,7287.5 3942.5,7287.5
VCC on Top Layer (solid, remove dead copper, pour order 26): 3060,4615 4425,4615 4425,5845 3060,5845
AGND on Bottom Layer (solid, remove dead copper, pour order 22): 4380,3950 4780,3950 4780,3115 7515,3115 7515,5325 4380,5325
VL_B_1 on Top Layer (solid, remove dead copper, pour order 4): 4940,4695 4940,3340 5505,3340 5505,4225 5580,4300 6070,4300 6150,4220 6150,3925 6260,3815 6405,3815 6405,4845 4935,4845 4935,4700
V+LED_B_1 on Top Layer (solid, remove dead copper, pour order 6): 5505,3360 6889.36,3360 6889.36,3855 7670,3855 7670,4180 6150,4180 6150,4220 6070,4300 5580,4300 5505,4225
VL_B_2 on Top Layer (solid, remove dead copper, pour order 10): 4939.28,5587.55 4939.28,6942.55 5504.28,6942.55 5504.28,6057.55 5579.28,5982.55 6069.28,5982.55 6149.28,6062.55 6149.28,6357.55 6259.28,6467.55 6404.28,6467.55 6404.28,5437.55 4934.28,5437.55 4934.28,5582.55
V+LED_B_2 on Top Layer (solid, remove dead copper, pour order 12): 5506,6919.54 6895.35,6919.54 6895.35,6434.54 7671,6434.54 7671,6099.54 6151,6099.54 6151,6059.54 6071,5979.54 5581,5979.54 5506,6054.54
+5V on Top Layer (solid, remove dead copper, pour order 16): 3975,7250 3350,7250 3350,5835 4380,5835 4380,6250 3975,6250
no net on Top Layer (solid, remove dead copper, pour order 18): 3975,7250 3975,6250 4380,6250 4380,3950 3915,3950 3915,3065.31 7590,3065.31 7590,7250
AGND on Bottom Layer (solid, remove dead copper, pour order 42): 4380,6355 4780,6355 4780,7190 7515,7190 7515,4980 4380,4980
AGND on Bottom Layer (solid, remove dead copper, pour order 48): 3935,7280 3935,6355 4375,6355 4375,3950 3880,3950 3880,3015 3295,3015 3295,7280

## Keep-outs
Board Outline Layer:
  lines w10: 3460,3140 7460,3140 7460,7140 3460,7140 3460,3140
